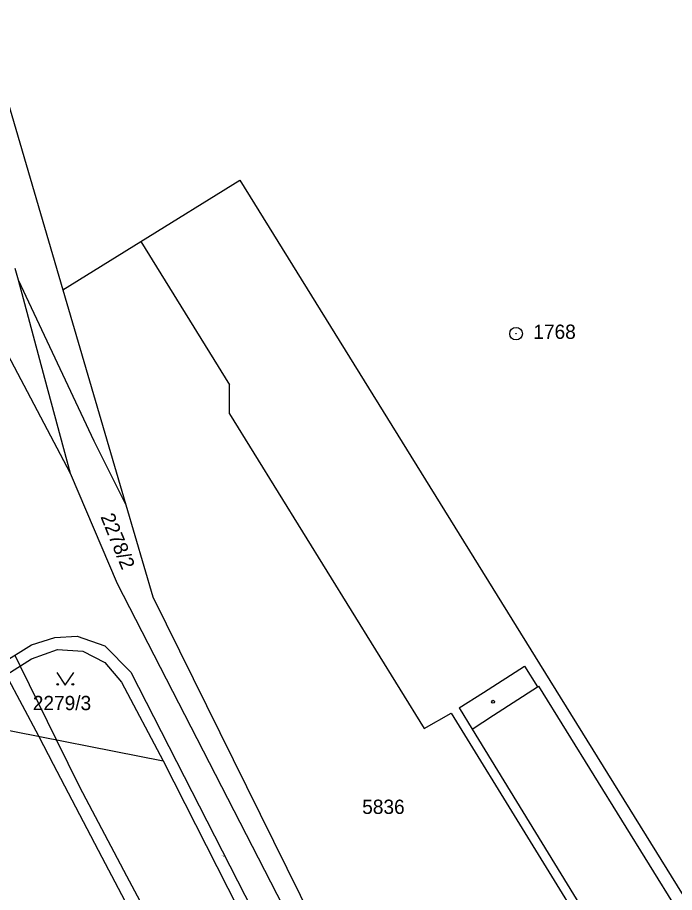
# Model space of a CAD drawing. Extents: x -735092 to -733385, y -1122435 to -1118992.
# Drawn here: x -734763.1 to -734684.8, y -1119634.5 to -1119530.3 of the extents above; entities that cross this region are included whole.
import ezdxf

# ---------------------------------------------------------------- set-up
doc = ezdxf.new("R2010")
doc.units = 0
for name, color, linetype in [('Vrstva 1', 7, 'Continuous'), ('Vrstva 17', 7, 'Continuous'), ('Vrstva 18', 7, 'Continuous'), ('Vrstva 25', 7, 'Continuous'), ('Vrstva 27', 7, 'Continuous'), ('Vrstva 4', 7, 'Continuous')]:
    doc.layers.add(name, color=color, linetype=linetype)

msp = doc.modelspace()

# ---------------------------------------------------------------- linework, layer by layer
at = {"layer": 'Vrstva 1'}
for points in [[(-734767.23, -1119530.27), (-734757.72, -1119562.71)], [(-734748.42, -1119556.94), (-734736.64, -1119549.63)], [(-734736.64, -1119549.63), (-734699.69, -1119609.22)], [(-734757.72, -1119562.71), (-734748.42, -1119556.94)], [(-734748.42, -1119556.94), (-734737.85, -1119574.01)], [(-734763.42, -1119560.13), (-734763.05, -1119561.5)], [(-734763.05, -1119561.5), (-734754.01, -1119580.7)], [(-734763.05, -1119561.5), (-734759.89, -1119573.21)], [(-734757.72, -1119562.71), (-734750.22, -1119588.3)], [(-734759.89, -1119573.21), (-734756.83, -1119584.56)], [(-734737.87, -1119577.47), (-734737.85, -1119574.01)], [(-734737.87, -1119577.47), (-734714.64, -1119614.94)], [(-734754.01, -1119580.7), (-734750.22, -1119588.3)], [(-734756.83, -1119584.56), (-734751.23, -1119597.69)], [(-734750.22, -1119588.3), (-734747, -1119599.28)], [(-734751.23, -1119597.69), (-734724.18, -1119650.29)], [(-734747, -1119599.28), (-734715.05, -1119663.89)], [(-734761.43, -1119604.98), (-734758.65, -1119604.12)], [(-734758.65, -1119604.12), (-734755.99, -1119603.97)], [(-734755.99, -1119603.97), (-734752.72, -1119605.1)], [(-734765.14, -1119607.29), (-734761.43, -1119604.98)], [(-734752.72, -1119605.1), (-734749.6, -1119608.25)], [(-734761.44, -1119606.67), (-734758.35, -1119605.56)], [(-734758.35, -1119605.56), (-734755.31, -1119605.76)], [(-734755.31, -1119605.76), (-734752.7, -1119607.11)], [(-734776.63, -1119616.25), (-734761.44, -1119606.67)], [(-734752.7, -1119607.11), (-734750.73, -1119609.44)], [(-734749.6, -1119608.25), (-734723.31, -1119659.67)], [(-734699.69, -1119609.22), (-734666.16, -1119663.28)], [(-734750.73, -1119609.44), (-734745.75, -1119618.79)], [(-734714.64, -1119614.94), (-734711.44, -1119613.13)], [(-734711.44, -1119613.13), (-734684.16, -1119657.42)], [(-734766.34, -1119614.74), (-734745.75, -1119618.79)], [(-734745.75, -1119618.79), (-734727.81, -1119654.13)]]:
    msp.add_lwpolyline(points, dxfattribs=at)
at = {"layer": 'Vrstva 25'}
msp.add_lwpolyline([(-734758.42, -1119608.3), (-734757.42, -1119609.8), (-734756.42, -1119608.3)], dxfattribs=at)
for centre, radius in [((-734703.71, -1119567.93), 0.75), ((-734703.71, -1119567.93), 0.032), ((-734758.32, -1119609.7), 0.1), ((-734756.52, -1119609.7), 0.1), ((-734706.45, -1119611.77), 0.175)]:
    msp.add_circle(centre, radius, dxfattribs=at)
at = {"layer": 'Vrstva 27'}
for points in [[(-734763.44, -1119606.24), (-734762.8, -1119607.53)], [(-734762.8, -1119607.53), (-734758.5, -1119616.28)], [(-734760.59, -1119615.87), (-734764.46, -1119608.57)], [(-734758.81, -1119619.23), (-734760.59, -1119615.87)], [(-734758.5, -1119616.28), (-734755.73, -1119621.91)], [(-734753.02, -1119630.31), (-734758.81, -1119619.23)], [(-734755.73, -1119621.91), (-734750.11, -1119632.49)], [(-734746.8, -1119642.16), (-734753.02, -1119630.31)], [(-734750.11, -1119632.49), (-734744.48, -1119643.08)]]:
    msp.add_lwpolyline(points, dxfattribs=at)
at = {"layer": 'Vrstva 4'}
for points in [[(-734768.29, -1119562.92), (-734756.83, -1119584.56)], [(-734707.6, -1119610.67), (-734702.7, -1119607.53)], [(-734702.7, -1119607.53), (-734701.17, -1119609.99)], [(-734706.38, -1119613.37), (-734701.17, -1119609.99)], [(-734701.17, -1119609.99), (-734701.04, -1119609.9)], [(-734701.04, -1119609.9), (-734674.67, -1119652.46)], [(-734710.47, -1119612.51), (-734707.6, -1119610.67)], [(-734710.47, -1119612.51), (-734708.92, -1119615.03)], [(-734708.92, -1119615.03), (-734706.38, -1119613.37)], [(-734708.92, -1119615.03), (-734683.3, -1119656.89)]]:
    msp.add_lwpolyline(points, dxfattribs=at)

# ---------------------------------------------------------------- texts
at = {"layer": 'Vrstva 17'}
msp.add_text('1768', height=1.7, dxfattribs=at).set_placement((-734701.65, -1119568.55))
at = {"layer": 'Vrstva 18'}
msp.add_text('2278/2', height=1.7, rotation=292.10232, dxfattribs=at).set_placement((-734753.25, -1119589.73))
for s, height, p in [('2279/3', 1.7, (-734761.29, -1119612.77)), ('5836', 1.7, (-734722.04, -1119625.13)), ('2279/2', 0.1, (-734738.81, -1119630.22))]:
    msp.add_text(s, height=height, dxfattribs=at).set_placement(p)

doc.saveas('drawing.dxf')
